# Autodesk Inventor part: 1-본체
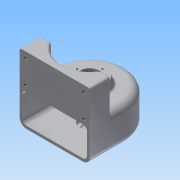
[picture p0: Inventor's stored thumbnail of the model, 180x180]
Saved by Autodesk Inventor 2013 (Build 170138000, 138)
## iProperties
Created: 2015-02
Part Number: 1-본체
Material: 알루미늄 6061
Document SubType Name: Modeling
Designer: Administrator
Density: 2.40731 g/cm^3
Mass: 511.46 g
Surface Area: 707.565 cm^2
Volume: 212.461 cm^3
Author: Administrator
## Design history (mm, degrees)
sketch "스케치1"
  geometry: L1 (-50, 0)-(-50, -50); L2 (-50, -50)-(50, -50); L3 (50, -50)-(50, 0); A1 r 50 centre (0, 0) between (-50, 0) and (50, 0); 1 further point
  constraints: 6 end point, 2 point on circle, 2 tangent, 2 vertical, 1 centre point, 1 coincident, 1 perpendicular
  dimensions: "d0" = 50 radius of A1; "d2" = 50 distance from line of L2 point (0, 0)
extrude "돌출1" new body sketch "스케치1" stored distance "d3" = 50; taper "d4" = 0 deg
sketch "스케치2"
  geometry: L1 (-50, 0)-(-50, -50) reference; L2 (-50, -50)-(50, -50) reference; L3 (50, -50)-(50, 0) reference; L4 (-50, -20)-(-34.641, -20); L5 (34.641, -20)-(50, -20); A1 r 50 centre (0, 0) between (50, 0) and (-50, 0) reference; A2 r 40 centre (0, 0) between (-34.641, -20) and (34.641, -20)
  constraints: 4 end point, 2 collinear, 2 point on circle, 2 point on line, 1 centre point, 1 coincident, 1 perpendicular
  dimensions: "d5" = 40 radius of A2; "d7" = 30 distance between parallel lines of L2 L5
extrude "돌출2" join sketch "스케치2" distance "d8" = 45; taper "d9" = 0 deg
node "작업 평면1"
sketch "스케치3"
  geometry: L1 (-50, 0)-(-50, -50) reference; L2 (50, -50)-(50, 0) reference; L3 (-50, -50)-(50, -50) reference; L4 (46, 0)-(46, -50); L5 (-46, -50)-(-46, 0); L6 (-46, -50)-(46, -50); A1 r 50 centre (0, 0) between (50, 0) and (-50, 0) reference; A2 r 46 centre (0, 0) between (46, 0) and (-46, 0); 1 further point
  constraints: 6 end point, 2 point on circle, 2 point on line, 1 centre point, 1 collinear
  dimensions: "d11" = 4 radial gap between concentric circles of A1 A2; "d12" = 4 distance between parallel lines of L1 L5; "d13" = 4 distance between parallel lines of L2 L4
extrude "돌출3" cut sketch "스케치3" distance "d14" = 42; taper "d15" = 0 deg
sketch "스케치4"
  geometry: C1 r 25 at (0, 0); A1 r 40 centre (0, 0) between (-34.641, -20) and (34.641, -20) reference
  constraints: 1 centre point, 1 coincident
  dimensions: "d16" = 50 diameter of C1
extrude "돌출4" join sketch "스케치4" distance "d18" = 10; taper "d19" = -20 deg
sketch "스케치5"
  geometry: C1 r 20 at (0, 0); A1 r 50 centre (0, 0) between (50, 0) and (-50, 0) reference
  constraints: 1 centre point, 1 coincident
  dimensions: "d20" = 40 diameter of C1
extrude "돌출5" join sketch "스케치5" distance "d22" = 9; taper "d23" = 0 deg
sketch "스케치6"
  geometry: L1 (100, 0)-(100, 95) reference; L2 (0, 95)-(100, 95) reference; 5 further points
  constraints: 2 horizontal alignment, 2 vertical alignment
  dimensions: "d24" = 33 distance of point (91.75, 53) point (91.75, 86); "d26" = 9 distance from line of point (91.75, 86) L2; "d27" = 83.5 distance of point (91.75, 86) point (8.25, 86); "d28" = 8.25 distance from line of L1 point (91.75, 86)
hole "구멍1" sketch "스케치6" at (8.25, 86), (8.25, 53), (91.75, 86), (91.75, 53) diameter "d29" = 5.134; stored, may be unused: countersink angle "d33" = 90 deg, drill point angle "d35" = 118 deg; dims "d30" = 10, "d31" = 4, "d32" = 2, "d34" = 13
hole "구멍2" diameter "d38" = 20; stored, may be unused: countersink angle "d42" = 90 deg, drill point angle "d44" = 0 deg; dims "d36" = 10, "d37" = 10, "d39" = 10, "d40" = 28, "d41" = 10, "d43" = 14
hole "구멍3" diameter "d47" = 20; stored, may be unused: countersink angle "d51" = 90 deg, drill point angle "d53" = 0 deg; dims "d45" = 10, "d46" = 10, "d48" = 10, "d49" = 28, "d50" = 8, "d52" = 10
sketch "스케치7"
  geometry: L1 (0, 18)-(-18, 0); L2 (-18, 0)-(0, -18); L3 (0, -18)-(18, 0); L4 (18, 0)-(0, 18); C1 r 14 at (0, 0) reference; 4 further points
  constraints: 8 end point, 4 coincident, 2 horizontal alignment, 2 parallel, 2 vertical alignment, 1 perpendicular
  dimensions: "d54" = 36 distance of L3.end L1.end
hole "구멍4" sketch "스케치7" at (0, 18), (18, 0), (0, -18), (-18, 0) diameter "d56" = 2.459; stored, may be unused: countersink angle "d60" = 90 deg, drill point angle "d62" = 118 deg; dims "d57" = 6, "d58" = 28, "d59" = 8, "d61" = 9
node "작업 평면2"
sketch "스케치8"
  geometry: L1 (-50, -25)-(50, -25) reference; 2 further points
  constraints: 1 coincident, 1 other
  dimensions: "d63" = 25 distance from line of point (0, 0) L1
feature "엠보싱1" sketch "스케치8" dims "d0" = 50, "d2" = 50, "d8" = 45, "d64" = 0.5, "d65" = 0
fillet "모깎기1" dims "d66" = 10, "d67" = 6, "d68" = 0.3
fillet "모깎기2" dims "d69" = 3
fillet "모깎기3" dims "d70" = 3
node "솔리드1"
other parameters: "d10" = -4
